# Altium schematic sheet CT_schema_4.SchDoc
size 258 x 142 mm
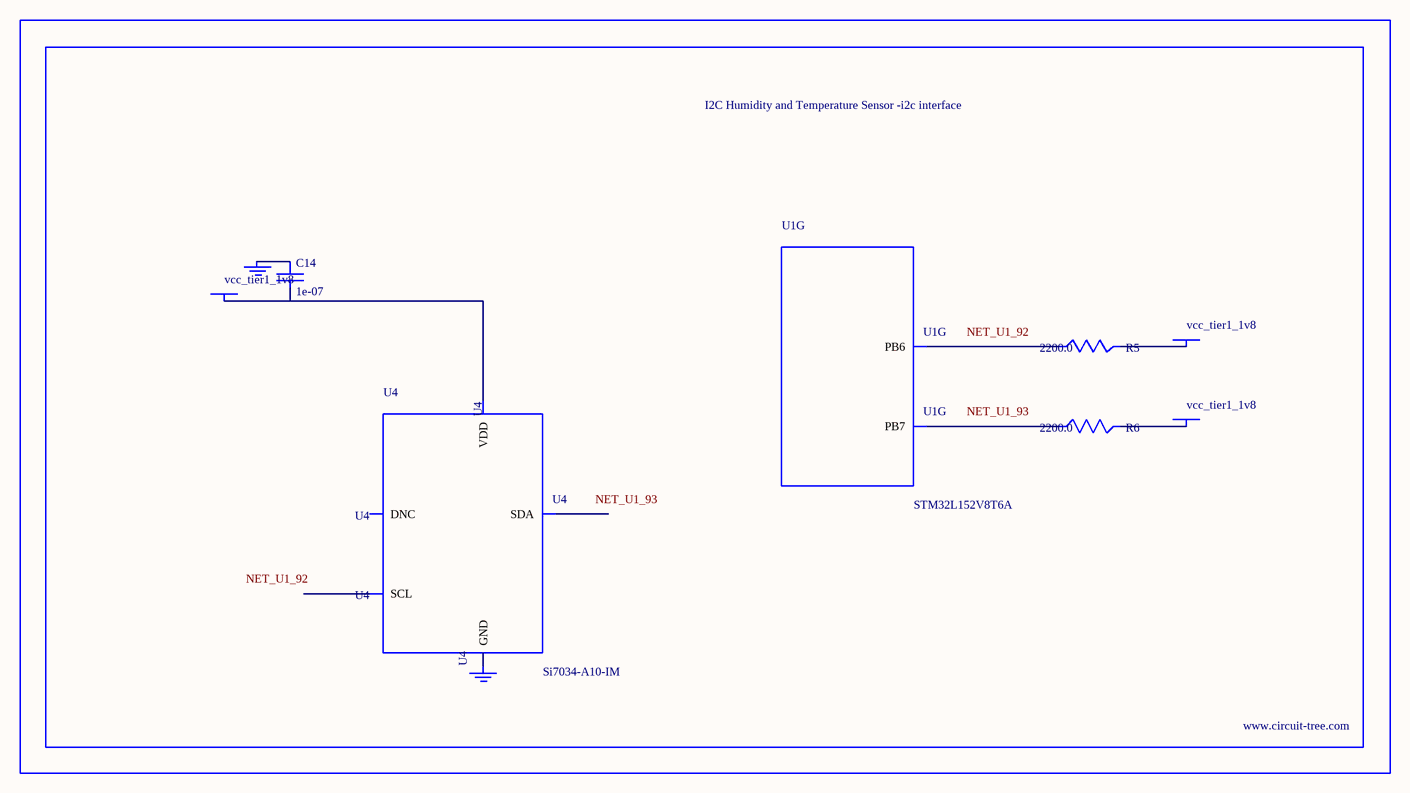
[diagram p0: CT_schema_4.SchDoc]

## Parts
BORDER3  (no value)
C14  1e-07  [C0402]
GND_INSTANCE_3_0  (no value)
GND_INSTANCE_3_1  (no value)
POWER_INSTANCE_3_0  vcc_tier1_1v8
POWER_INSTANCE_3_1  vcc_tier1_1v8
POWER_INSTANCE_3_2  vcc_tier1_1v8
R5  2200.0  [R0603]
R6  2200.0  [R0603]
U1  STM32L152V8T6A  [LQFP100]  (part G of 9)
U4  Si7034-A10-IM  [SI7034-A10-IM]

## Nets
NetC14_1: C14.1 GND_INSTANCE_3_0.0(GND)
NetC14_2: C14.2 POWER_INSTANCE_3_0.0(PWR) U4.1(VDD)
NetGND_INSTANCE_3_1_0: GND_INSTANCE_3_1.0(GND) U4.5(GND)
NetPOWER_INSTANCE_3_1_0: POWER_INSTANCE_3_1.0(PWR) R5.2
NetPOWER_INSTANCE_3_2_0: POWER_INSTANCE_3_2.0(PWR) R6.2
NetR5_1: R5.1 U1.92(PB6)
NetR6_1: R6.1 U1.93(PB7)

Not connected (* = marked no-connect by the designer): U4 2(SCL) 3(DNC) 4(SDA)

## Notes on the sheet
- Labels drawn without touching a wire or pin: NET_U1_92, NET_U1_93

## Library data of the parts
BORDER3 = BORDER_PAGE3
C14 = C0402C104K3RACTU
GND_INSTANCE_3_0 GND_INSTANCE_3_1 = GND
POWER_INSTANCE_3_0-POWER_INSTANCE_3_2 = PWR
R5 R6 = RC0603JR-072K2L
